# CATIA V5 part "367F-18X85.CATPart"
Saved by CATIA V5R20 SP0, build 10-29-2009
Part number: 367F-18X85
Definition: NONE
Nomenclature: 367F-18X85
Source: Unknown
Description: 367F-18X85
Bounding box of the stored display mesh (mm): x 0 to 85, y -14 to 14, z -14 to 14
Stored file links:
  C:\Users\Utente\Desktop\IO LAVORO\3D X SITO CF\X SITO\PLASTICA\3D files 367\367F-18X85.CATPart
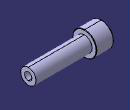
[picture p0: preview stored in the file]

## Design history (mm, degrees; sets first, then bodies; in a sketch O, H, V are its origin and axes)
Body1 "367F-18X85" (main body)
  Solid1: solid without history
